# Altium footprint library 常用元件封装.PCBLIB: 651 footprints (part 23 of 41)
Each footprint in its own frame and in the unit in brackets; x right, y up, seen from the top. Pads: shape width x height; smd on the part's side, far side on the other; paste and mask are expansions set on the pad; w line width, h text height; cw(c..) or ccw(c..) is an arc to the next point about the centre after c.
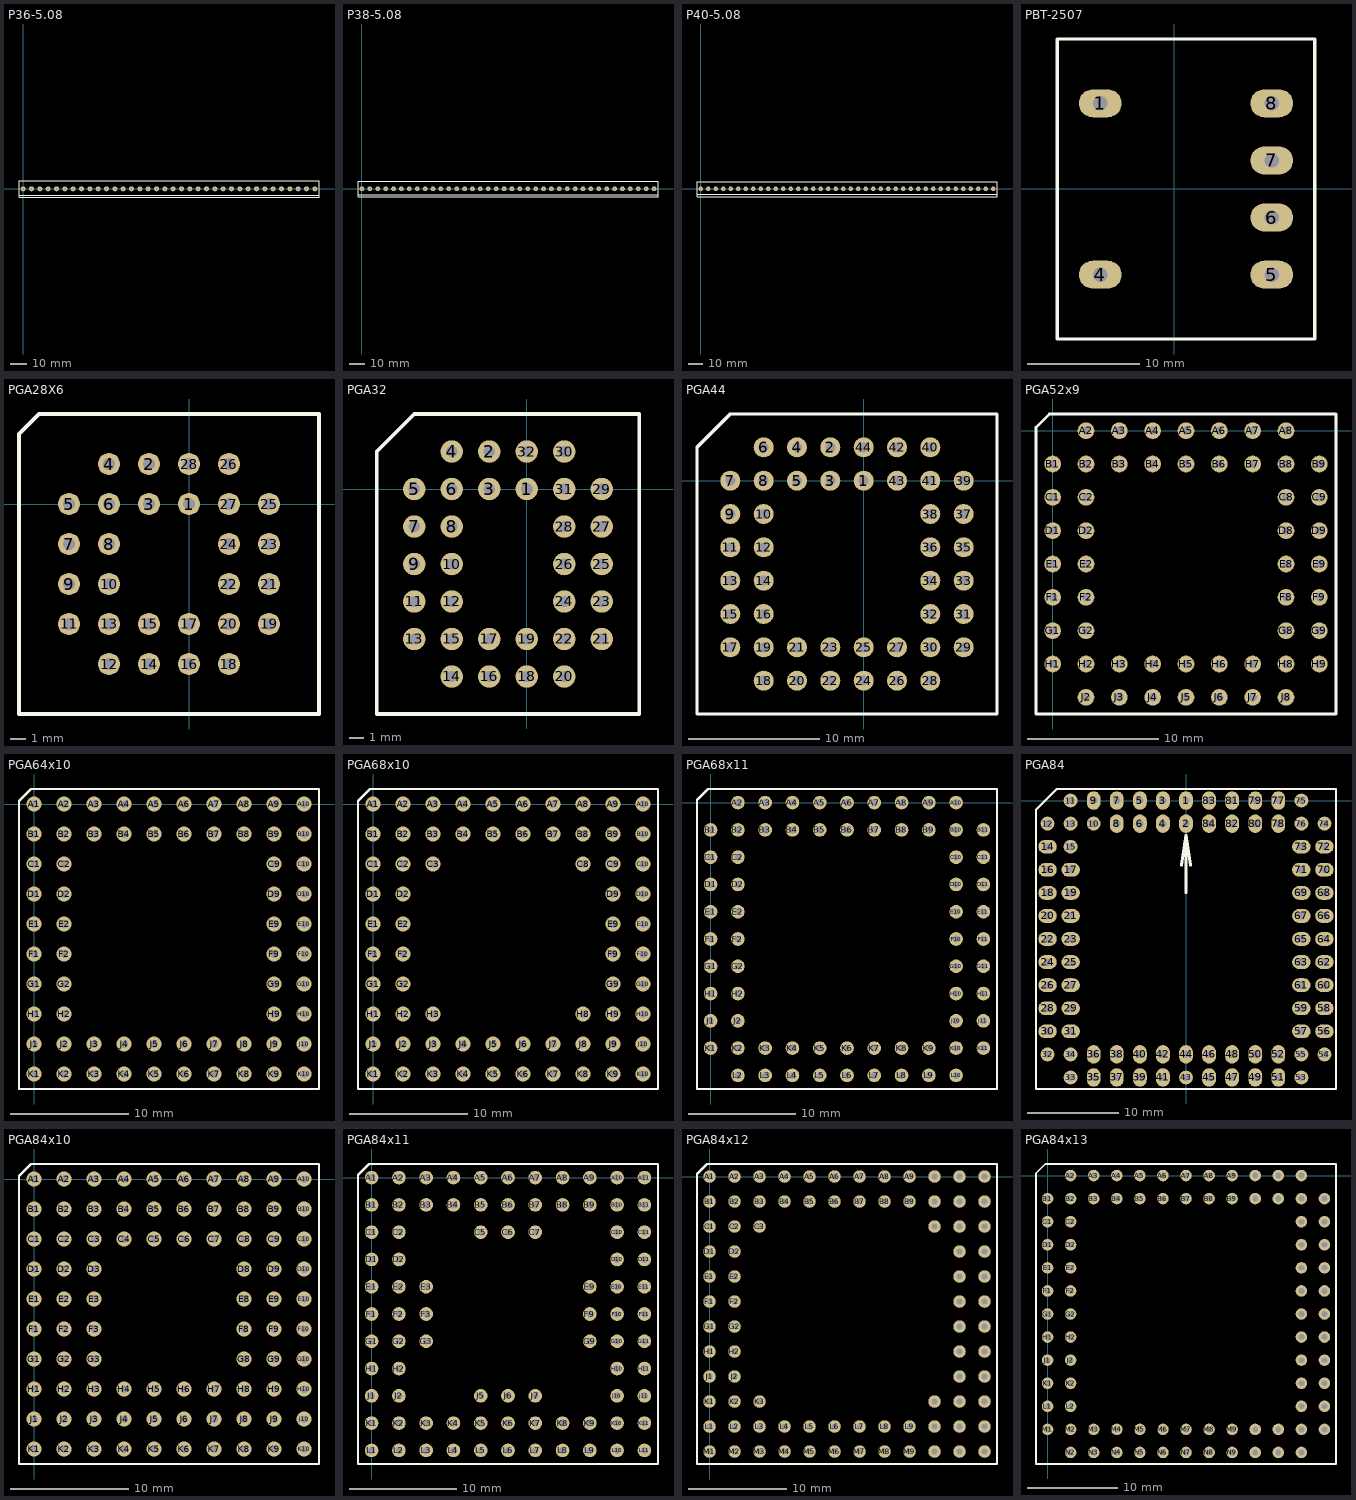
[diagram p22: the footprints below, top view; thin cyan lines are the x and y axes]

## P36-5.08 [mil]
height 543.31
pads (36):
  round 120 hole 50: 0(0,0) 1(200,0) 2(400,0) 3(600,0) 4(800,0) 5(1000,0) 6(1200,0) 7(1400,0) 8(1600,0) 9(1800,0) 10(2000,0) 11(2200,0) 12(2400,0) 13(2600,0) 14(2800,0) 15(3000,0) 16(3200,0) 17(3400,0) 18(3600,0) 19(3800,0) 20(4000,0) 21(4200,0) 22(4400,0) 23(4600,0) 24(4800,0) 25(5000,0) 26(5200,0) 27(5400,0) 28(5600,0) 29(5800,0) 30(6000,0) 31(6200,0) 32(6400,0) 33(6600,0) 34(6800,0) 35(7000,0)
TopOverlay:
  lines w6.69: -100,-150 7100,-150 ; -100,-205 7100,-205 7100,195 -100,195 -100,-205

## P38-5.08 [mil]
height 543.31
pads (38):
  round 120 hole 50: 0(0,0) 1(200,0) 2(400,0) 3(600,0) 4(800,0) 5(1000,0) 6(1200,0) 7(1400,0) 8(1600,0) 9(1800,0) 10(2000,0) 11(2200,0) 12(2400,0) 13(2600,0) 14(2800,0) 15(3000,0) 16(3200,0) 17(3400,0) 18(3600,0) 19(3800,0) 20(4000,0) 21(4200,0) 22(4400,0) 23(4600,0) 24(4800,0) 25(5000,0) 26(5200,0) 27(5400,0) 28(5600,0) 29(5800,0) 30(6000,0) 31(6200,0) 32(6400,0) 33(6600,0) 34(6800,0) 35(7000,0) 36(7200,0) 37(7400,0)
TopOverlay:
  lines w6.69: -100,-150 7500,-150 ; -100,-205 7500,-205 7500,195 -100,195 -100,-205

## P40-5.08 [mil]
height 543.31
pads (40):
  round 120 hole 50: 0(0,0) 1(200,0) 2(400,0) 3(600,0) 4(800,0) 5(1000,0) 6(1200,0) 7(1400,0) 8(1600,0) 9(1800,0) 10(2000,0) 11(2200,0) 12(2400,0) 13(2600,0) 14(2800,0) 15(3000,0) 16(3200,0) 17(3400,0) 18(3600,0) 19(3800,0) 20(4000,0) 21(4200,0) 22(4400,0) 23(4600,0) 24(4800,0) 25(5000,0) 26(5200,0) 27(5400,0) 28(5600,0) 29(5800,0) 30(6000,0) 31(6200,0) 32(6400,0) 33(6600,0) 34(6800,0) 35(7000,0) 36(7200,0) 37(7400,0) 38(7600,0) 39(7800,0)
TopOverlay:
  lines w6.69: -100,-150 7900,-150 ; -100,-205 7900,-205 7900,195 -100,195 -100,-205

## PBT-2507 [mil]
pads (6):
  oval 150x98 hole 50: 1(-259,299) 4(-259,-301) 5(341,-301) 6(341,-101) 7(341,99) 8(341,299)
TopOverlay:
  lines w12: -409,-526 491,-526 491,524 -409,524 -409,-526

## PGA28X6 [mil]
pads (28):
  round 55 hole 30: 1(0,0) 2(-100,100) 3(-100,0) 4(-200,100) 5(-300,0) 6(-200,0) 7(-300,-100) 8(-200,-100) 9(-300,-200) 10(-200,-200) 11(-300,-300) 12(-200,-400) 13(-200,-300) 14(-100,-400) 15(-100,-300) 16(0,-400) 17(0,-300) 18(100,-400) 19(200,-300) 20(100,-300) 21(200,-200) 22(100,-200) 23(200,-100) 24(100,-100) 25(200,0) 26(100,100) 27(100,0) 28(0,100)
TopOverlay:
  lines w10: -425,-525 -425,175 -375,225 -350,225 325,225 325,-525 -425,-525

## PGA32 [mil]
pads (32):
  round 60 hole 32: 1(0,0)
  round 60 hole 30: 2(-100,100) 3(-100,0) 4(-200,100) 5(-300,0) 6(-200,0) 7(-300,-100) 8(-200,-100) 9(-300,-200) 10(-200,-200) 11(-300,-300) 12(-200,-300) 13(-300,-400) 14(-200,-500) 15(-200,-400) 16(-100,-500) 17(-100,-400) 18(0,-500) 19(0,-400) 20(100,-500) 21(200,-400) 22(100,-400) 23(200,-300) 24(100,-300) 25(200,-200) 26(100,-200) 27(200,-100) 28(100,-100) 29(200,0) 30(100,100) 31(100,0) 32(0,100)
TopOverlay:
  lines w10: -400,-600 300,-600 300,200 -300,200 -400,100 -400,-600

## PGA44 [mil]
pads (44):
  round 60 hole 30: 1(0,0) 2(-100,100) 3(-100,0) 4(-200,100) 5(-200,0) 6(-300,100) 7(-400,0) 8(-300,0) 9(-400,-100) 10(-300,-100) 11(-400,-200) 12(-300,-200) 13(-400,-300) 14(-300,-300) 15(-400,-400) 16(-300,-400) 17(-400,-500) 18(-300,-600) 19(-300,-500) 20(-200,-600) 21(-200,-500) 22(-100,-600) 23(-100,-500) 24(0,-600) 25(0,-500) 26(100,-600) 27(100,-500) 28(200,-600) 29(300,-500) 30(200,-500) 31(300,-400) 32(200,-400) 33(300,-300) 34(200,-300) 35(300,-200) 36(200,-200) 37(300,-100) 38(200,-100) 39(300,0) 40(200,100) 41(200,0) 42(100,100) 43(100,0) 44(0,100)
TopOverlay:
  lines w10: -500,-700 -500,100 -400,200 400,200 400,-700 -500,-700

## PGA52x9 [mil]
pads (52):
  round 50 hole 25: A2(100,0) A3(200,0) A4(300,0) A5(400,0) A6(500,0) A7(600,0) A8(700,0) B1(0,-100) B2(100,-100) B3(200,-100) B4(300,-100) B5(400,-100) B6(500,-100) B7(600,-100) B8(700,-100) B9(800,-100) C1(0,-200) C2(100,-200) C8(700,-200) C9(800,-200) D1(0,-300) D2(100,-300) D8(700,-300) D9(800,-300) E1(0,-400) E2(100,-400) E8(700,-400) E9(800,-400) F1(0,-500) F2(100,-500) F8(700,-500) F9(800,-500) G1(0,-600) G2(100,-600) G8(700,-600) G9(800,-600) H1(0,-700) H2(100,-700) H3(200,-700) H4(300,-700) H5(400,-700) H6(500,-700) H7(600,-700) H8(700,-700) H9(800,-700) J2(100,-800) J3(200,-800) J4(300,-800) J5(400,-800) J6(500,-800) J7(600,-800) J8(700,-800)
TopOverlay:
  lines w8: -50,-850 -50,10 -10,50 850,50 850,-850 -50,-850

## PGA64x10 [mil]
pads (64):
  round 50 hole 25: A1(0,0) A2(100,0) A3(200,0) A4(300,0) A5(400,0) A6(500,0) A7(600,0) A8(700,0) A9(800,0) A10(900,0) B1(0,-100) B2(100,-100) B3(200,-100) B4(300,-100) B5(400,-100) B6(500,-100) B7(600,-100) B8(700,-100) B9(800,-100) B10(900,-100) C1(0,-200) C2(100,-200) C9(800,-200) C10(900,-200) D1(0,-300) D2(100,-300) D9(800,-300) D10(900,-300) E1(0,-400) E2(100,-400) E9(800,-400) E10(900,-400) F1(0,-500) F2(100,-500) F9(800,-500) F10(900,-500) G1(0,-600) G2(100,-600) G9(800,-600) G10(900,-600) H1(0,-700) H2(100,-700) H9(800,-700) H10(900,-700) J1(0,-800) J2(100,-800) J3(200,-800) J4(300,-800) J5(400,-800) J6(500,-800) J7(600,-800) J8(700,-800) J9(800,-800) J10(900,-800) K1(0,-900) K2(100,-900) K3(200,-900) K4(300,-900) K5(400,-900) K6(500,-900) K7(600,-900) K8(700,-900) K9(800,-900) K10(900,-900)
TopOverlay:
  lines w8: -50,-950 -50,10 -10,50 950,50 950,-950 -50,-950

## PGA68x10 [mil]
pads (68):
  round 50 hole 25: A1(0,0) A2(100,0) A3(200,0) A4(300,0) A5(400,0) A6(500,0) A7(600,0) A8(700,0) A9(800,0) A10(900,0) B1(0,-100) B2(100,-100) B3(200,-100) B4(300,-100) B5(400,-100) B6(500,-100) B7(600,-100) B8(700,-100) B9(800,-100) B10(900,-100) C1(0,-200) C2(100,-200) C3(200,-200) C8(700,-200) C9(800,-200) C10(900,-200) D1(0,-300) D2(100,-300) D9(800,-300) D10(900,-300) E1(0,-400) E2(100,-400) E9(800,-400) E10(900,-400) F1(0,-500) F2(100,-500) F9(800,-500) F10(900,-500) G1(0,-600) G2(100,-600) G9(800,-600) G10(900,-600) H1(0,-700) H2(100,-700) H3(200,-700) H8(700,-700) H9(800,-700) H10(900,-700) J1(0,-800) J2(100,-800) J3(200,-800) J4(300,-800) J5(400,-800) J6(500,-800) J7(600,-800) J8(700,-800) J9(800,-800) J10(900,-800) K1(0,-900) K2(100,-900) K3(200,-900) K4(300,-900) K5(400,-900) K6(500,-900) K7(600,-900) K8(700,-900) K9(800,-900) K10(900,-900)
TopOverlay:
  lines w8: -50,-950 -50,10 -10,50 950,50 950,-950 -50,-950

## PGA68x11 [mil]
pads (68):
  round 50 hole 25: A2(100,0) A3(200,0) A4(300,0) A5(400,0) A6(500,0) A7(600,0) A8(700,0) A9(800,0) A10(900,0) B1(0,-100) B2(100,-100) B3(200,-100) B4(300,-100) B5(400,-100) B6(500,-100) B7(600,-100) B8(700,-100) B9(800,-100) B10(900,-100) B11(1000,-100) C1(0,-200) C2(100,-200) C10(900,-200) C11(1000,-200) D1(0,-300) D2(100,-300) D10(900,-300) D11(1000,-300) E1(0,-400) E2(100,-400) E10(900,-400) E11(1000,-400) F1(0,-500) F2(100,-500) F10(900,-500) F11(1000,-500) G1(0,-600) G2(100,-600) G10(900,-600) G11(1000,-600) H1(0,-700) H2(100,-700) H10(900,-700) H11(1000,-700) J1(0,-800) J2(100,-800) J10(900,-800) J11(1000,-800) K1(0,-900) K2(100,-900) K3(200,-900) K4(300,-900) K5(400,-900) K6(500,-900) K7(600,-900) K8(700,-900) K9(800,-900) K10(900,-900) K11(1000,-900) L2(100,-1000) L3(200,-1000) L4(300,-1000) L5(400,-1000) L6(500,-1000) L7(600,-1000) L8(700,-1000) L9(800,-1000) L10(900,-1000)
TopOverlay:
  lines w8: -50,-1050 -50,10 -10,50 1050,50 1050,-1050 -50,-1050

## PGA84 [mil]
pads (84):
  oval 60x80 hole 32: 1(0,0) 2(0,-100) 3(-100,0) 4(-100,-100) 5(-200,0) 6(-200,-100) 7(-300,0) 8(-300,-100) 9(-400,0) 35(-400,-1200) 36(-400,-1100) 37(-300,-1200) 38(-300,-1100) 39(-200,-1200) 40(-200,-1100) 41(-100,-1200) 42(-100,-1100) 44(0,-1100) 45(100,-1200) 46(100,-1100) 47(200,-1200) 48(200,-1100) 49(300,-1200) 50(300,-1100) 51(400,-1200) 52(400,-1100) 77(400,0) 78(400,-100) 79(300,0) 80(300,-100) 81(200,0) 82(200,-100) 83(100,0) 84(100,-100)
  round 60 hole 32: 10(-400,-100) 11(-500,0) 12(-600,-100) 13(-500,-100) 15(-500,-200) 32(-600,-1100) 33(-500,-1200) 34(-500,-1100) 43(0,-1200) 53(500,-1200) 54(600,-1100) 55(500,-1100) 74(600,-100) 75(500,0) 76(500,-100)
  oval 80x60 hole 32: 14(-600,-200) 16(-600,-300) 17(-500,-300) 18(-600,-400) 19(-500,-400) 20(-600,-500) 21(-500,-500) 22(-600,-600) 23(-500,-600) 24(-600,-700) 25(-500,-700) 26(-600,-800) 27(-500,-800) 28(-600,-900) 29(-500,-900) 30(-600,-1000) 31(-500,-1000) 56(600,-1000) 57(500,-1000) 58(600,-900) 59(500,-900) 60(600,-800) 61(500,-800) 62(600,-700) 63(500,-700) 64(600,-600) 65(500,-600) 66(600,-500) 67(500,-500) 68(600,-400) 69(500,-400) 70(600,-300) 71(500,-300) 72(600,-200) 73(500,-200)
TopOverlay:
  lines w10: -650,-1250 -650,-40 -560,50 650,50 650,-1250 -650,-1250
  lines w12: -20,-280 0,-150 ; 0,-400 0,-150 ; 20,-280 0,-150

## PGA84x10 [mil]
pads (84):
  round 50 hole 25: A1(0,0) A2(100,0) A3(200,0) A4(300,0) A5(400,0) A6(500,0) A7(600,0) A8(700,0) A9(800,0) A10(900,0) B1(0,-100) B2(100,-100) B3(200,-100) B4(300,-100) B5(400,-100) B6(500,-100) B7(600,-100) B8(700,-100) B9(800,-100) B10(900,-100) C1(0,-200) C2(100,-200) C3(200,-200) C4(300,-200) C5(400,-200) C6(500,-200) C7(600,-200) C8(700,-200) C9(800,-200) C10(900,-200) D1(0,-300) D2(100,-300) D3(200,-300) D8(700,-300) D9(800,-300) D10(900,-300) E1(0,-400) E2(100,-400) E3(200,-400) E8(700,-400) E9(800,-400) E10(900,-400) F1(0,-500) F2(100,-500) F3(200,-500) F8(700,-500) F9(800,-500) F10(900,-500) G1(0,-600) G2(100,-600) G3(200,-600) G8(700,-600) G9(800,-600) G10(900,-600) H1(0,-700) H2(100,-700) H3(200,-700) H4(300,-700) H5(400,-700) H6(500,-700) H7(600,-700) H8(700,-700) H9(800,-700) H10(900,-700) J1(0,-800) J2(100,-800) J3(200,-800) J4(300,-800) J5(400,-800) J6(500,-800) J7(600,-800) J8(700,-800) J9(800,-800) J10(900,-800) K1(0,-900) K2(100,-900) K3(200,-900) K4(300,-900) K5(400,-900) K6(500,-900) K7(600,-900) K8(700,-900) K9(800,-900) K10(900,-900)
TopOverlay:
  lines w8: -50,-950 -50,10 -10,50 950,50 950,-950 -50,-950

## PGA84x11 [mil]
pads (84):
  round 50 hole 25: A1(0,0) A2(100,0) A3(200,0) A4(300,0) A5(400,0) A6(500,0) A7(600,0) A8(700,0) A9(800,0) A10(900,0) A11(1000,0) B1(0,-100) B2(100,-100) B3(200,-100) B4(300,-100) B5(400,-100) B6(500,-100) B7(600,-100) B8(700,-100) B9(800,-100) B10(900,-100) B11(1000,-100) C1(0,-200) C2(100,-200) C5(400,-200) C6(500,-200) C7(600,-200) C10(900,-200) C11(1000,-200) D1(0,-300) D2(100,-300) D10(900,-300) D11(1000,-300) E1(0,-400) E2(100,-400) E3(200,-400) E9(800,-400) E10(900,-400) E11(1000,-400) F1(0,-500) F2(100,-500) F3(200,-500) F9(800,-500) F10(900,-500) F11(1000,-500) G1(0,-600) G2(100,-600) G3(200,-600) G9(800,-600) G10(900,-600) G11(1000,-600) H1(0,-700) H2(100,-700) H10(900,-700) H11(1000,-700) J1(0,-800) J2(100,-800) J5(400,-800) J6(500,-800) J7(600,-800) J10(900,-800) J11(1000,-800) K1(0,-900) K2(100,-900) K3(200,-900) K4(300,-900) K5(400,-900) K6(500,-900) K7(600,-900) K8(700,-900) K9(800,-900) K10(900,-900) K11(1000,-900) L1(0,-1000) L2(100,-1000) L3(200,-1000) L4(300,-1000) L5(400,-1000) L6(500,-1000) L7(600,-1000) L8(700,-1000) L9(800,-1000) L10(900,-1000) L11(1000,-1000)
TopOverlay:
  lines w8: -50,-1050 1050,-1050 1050,50 -10,50 -50,10 -50,-1050

## PGA84x12 [mil]
pads (84):
  round 50 hole 25: A1(0,0) A2(100,0) A3(200,0) A4(300,0) A5(400,0) A6(500,0) A7(600,0) A8(700,0) A9(800,0) A10(900,0) A11(1000,0) A12(1100,0) B1(0,-100) B2(100,-100) B3(200,-100) B4(300,-100) B5(400,-100) B6(500,-100) B7(600,-100) B8(700,-100) B9(800,-100) B10(900,-100) B11(1000,-100) B12(1100,-100) C1(0,-200) C2(100,-200) C3(200,-200) C10(900,-200) C11(1000,-200) C12(1100,-200) D1(0,-300) D2(100,-300) D11(1000,-300) D12(1100,-300) E1(0,-400) E2(100,-400) E11(1000,-400) E12(1100,-400) F1(0,-500) F2(100,-500) F11(1000,-500) F12(1100,-500) G1(0,-600) G2(100,-600) G11(1000,-600) G12(1100,-600) H1(0,-700) H2(100,-700) H11(1000,-700) H12(1100,-700) J1(0,-800) J2(100,-800) J11(1000,-800) J12(1100,-800) K1(0,-900) K2(100,-900) K3(200,-900) K10(900,-900) K11(1000,-900) K12(1100,-900) L1(0,-1000) L2(100,-1000) L3(200,-1000) L4(300,-1000) L5(400,-1000) L6(500,-1000) L7(600,-1000) L8(700,-1000) L9(800,-1000) L10(900,-1000) L11(1000,-1000) L12(1100,-1000) M1(0,-1100) M2(100,-1100) M3(200,-1100) M4(300,-1100) M5(400,-1100) M6(500,-1100) M7(600,-1100) M8(700,-1100) M9(800,-1100) M10(900,-1100) M11(1000,-1100) M12(1100,-1100)
TopOverlay:
  lines w8: -50,-1150 1150,-1150 1150,50 -10,50 -50,10 -50,-1150

## PGA84x13 [mil]
pads (84):
  round 50 hole 25: A2(100,0) A3(200,0) A4(300,0) A5(400,0) A6(500,0) A7(600,0) A8(700,0) A9(800,0) A10(900,0) A11(1000,0) A12(1100,0) B1(0,-100) B2(100,-100) B3(200,-100) B4(300,-100) B5(400,-100) B6(500,-100) B7(600,-100) B8(700,-100) B9(800,-100) B10(900,-100) B11(1000,-100) B12(1100,-100) B13(1200,-100) C1(0,-200) C2(100,-200) C12(1100,-200) C13(1200,-200) D1(0,-300) D2(100,-300) D12(1100,-300) D13(1200,-300) E1(0,-400) E2(100,-400) E12(1100,-400) E13(1200,-400) F1(0,-500) F2(100,-500) F12(1100,-500) F13(1200,-500) G1(0,-600) G2(100,-600) G12(1100,-600) G13(1200,-600) H1(0,-700) H2(100,-700) H12(1100,-700) H13(1200,-700) J1(0,-800) J2(100,-800) J12(1100,-800) J13(1200,-800) K1(0,-900) K2(100,-900) K12(1100,-900) K13(1200,-900) L1(0,-1000) L2(100,-1000) L12(1100,-1000) L13(1200,-1000) M1(0,-1100) M2(100,-1100) M3(200,-1100) M4(300,-1100) M5(400,-1100) M6(500,-1100) M7(600,-1100) M8(700,-1100) M9(800,-1100) M10(900,-1100) M11(1000,-1100) M12(1100,-1100) M13(1200,-1100) N2(100,-1200) N3(200,-1200) N4(300,-1200) N5(400,-1200) N6(500,-1200) N7(600,-1200) N8(700,-1200) N9(800,-1200) N10(900,-1200) N11(1000,-1200) N12(1100,-1200)
TopOverlay:
  lines w8: -50,-1250 -50,10 -10,50 1250,50 1250,-1250 -50,-1250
